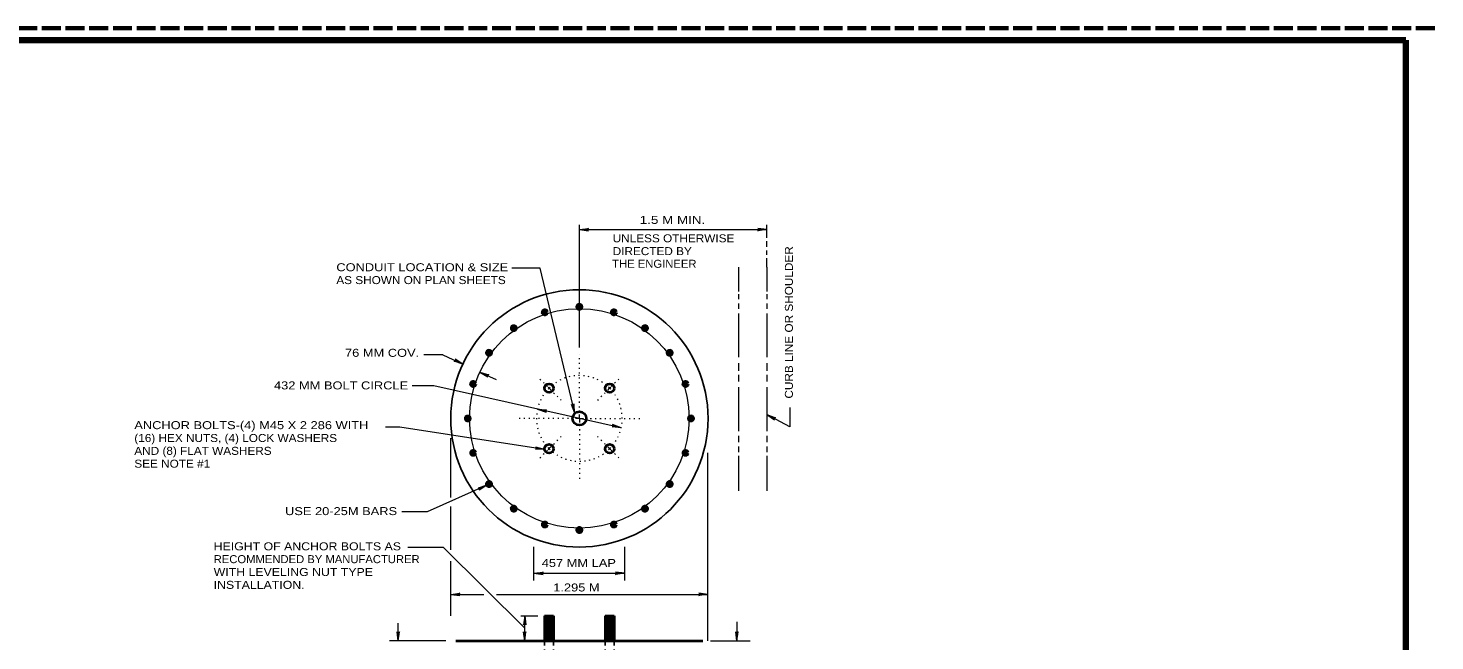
# Model space of a CAD drawing. Extents: x 312583 to 312853, y 144419 to 144586.
# Drawn here: x 312718.1 to 312851.8, y 144528 to 144586.2 of the extents above; entities that cross this region are included whole.
import ezdxf

# ---------------------------------------------------------------- set-up
doc = ezdxf.new("R2010")
doc.units = 0
doc.header["$LTSCALE"] = 0.3
for name, pattern in [('DOTTED', [1.5, 0.3, -1.2]), ('LONG_DASHED', [7.5, 6, -1.5]), ('SHORT_DASHED', [2.7, 1.5, -1.2])]:
    doc.linetypes.add(name, pattern=pattern)
doc.layers.add('1', color=7, linetype='Continuous', lineweight=13)
doc.layers.add('61', color=7, linetype='LONG_DASHED', lineweight=60)

msp = doc.modelspace()

# ---------------------------------------------------------------- linework, layer by layer
at = {"layer": '1', "lineweight": 158}
msp.add_line((312849, 144423.1446), (312849, 144585.0846), dxfattribs=at)
at = {"layer": '1'}
for p, q in [((312770.4975, 144555.8762), (312770.4975, 144567.5219)), ((312770.4975, 144567.0849), (312771.3638, 144567.1922)), ((312770.4975, 144567.0849), (312788.3148, 144567.0849)), ((312770.4975, 144567.0849), (312771.3638, 144566.9775)), ((312771.3638, 144567.1922), (312771.0878, 144567.0849)), ((312771.3638, 144566.9775), (312771.0878, 144567.0849)), ((312787.4485, 144567.1922), (312787.7245, 144567.0849)), ((312788.3148, 144567.0849), (312787.4485, 144567.1922)), ((312787.4485, 144566.9775), (312787.7245, 144567.0849)), ((312788.3148, 144567.0849), (312787.4485, 144566.9775)), ((312788.3148, 144566.3182), (312788.3148, 144567.5372)), ((312788.3148, 144565.4595), (312788.3148, 144565.9732)), ((312788.3148, 144564.6929), (312788.3148, 144565.1069)), ((312788.3148, 144563.5275), (312788.3148, 144564.3785)), ((312785.6085, 144563.5275), (312785.6085, 144561.2199)), ((312788.3148, 144563.5275), (312788.3148, 144561.2199)), ((312785.6085, 144560.9439), (312785.6085, 144560.4839)), ((312788.3148, 144560.9439), (312788.3148, 144560.4839)), ((312785.6085, 144560.0699), (312785.6085, 144559.5639)), ((312785.6085, 144559.1192), (312785.6085, 144554.9715)), ((312788.3148, 144560.0699), (312788.3148, 144559.5639)), ((312788.3148, 144559.1192), (312788.3148, 144554.9715)), ((312757.5408, 144555.1862), (312755.7162, 144555.1862)), ((312757.5408, 144555.1862), (312759.4192, 144554.3122)), ((312758.5912, 144554.5805), (312758.8825, 144554.5575)), ((312759.4192, 144554.3122), (312758.5912, 144554.5805)), ((312758.6832, 144554.7722), (312758.8825, 144554.5575)), ((312759.4192, 144554.3122), (312758.6832, 144554.7722)), ((312761.0522, 144553.5532), (312762.5778, 144552.8402)), ((312761.0522, 144553.5532), (312761.7882, 144553.0855)), ((312761.0522, 144553.5532), (312761.8802, 144553.2849)), ((312785.6085, 144554.4042), (312785.6085, 144553.6682)), ((312788.3148, 144554.4042), (312788.3148, 144553.6682)), ((312756.6668, 144552.2345), (312754.6045, 144552.2345)), ((312774.4688, 144548.2555), (312756.6668, 144552.2345)), ((312761.7882, 144553.0855), (312761.5812, 144553.3002)), ((312761.8802, 144553.2849), (312761.5812, 144553.3002)), ((312785.6085, 144553.3002), (312785.6085, 144552.6562)), ((312788.3148, 144553.3002), (312788.3148, 144552.6562)), ((312767.6148, 144552.0275), (312767.5152, 144552.1272)), ((312767.6148, 144552.0275), (312767.5152, 144551.9279)), ((312767.6148, 144552.0275), (312767.7145, 144552.1272)), ((312767.6148, 144552.0275), (312767.7145, 144551.9279)), ((312773.3725, 144552.0275), (312773.2728, 144552.1272)), ((312773.3725, 144552.0275), (312773.2728, 144551.9279)), ((312773.3725, 144552.0275), (312773.4798, 144552.1272)), ((312773.3725, 144552.0275), (312773.4798, 144551.9279)), ((312785.6085, 144552.1042), (312785.6085, 144547.9259)), ((312788.3148, 144552.1042), (312788.3148, 144547.9259)), ((312766.5185, 144550.0342), (312767.3388, 144549.7429)), ((312766.5185, 144550.0342), (312767.3848, 144549.9499)), ((312767.3848, 144549.9499), (312767.0935, 144549.9039)), ((312767.3388, 144549.7429), (312767.0935, 144549.9039)), ((312769.7615, 144550.4712), (312769.9302, 144550.2259)), ((312770.0682, 144549.6509), (312769.7615, 144550.4712)), ((312769.9762, 144550.5172), (312769.9302, 144550.2259)), ((312770.0682, 144549.6509), (312769.9762, 144550.5172)), ((312770.4975, 144549.1449), (312770.4975, 144549.5282)), ((312788.3148, 144549.5205), (312789.0278, 144549.0145)), ((312788.3148, 144549.5205), (312789.1275, 144549.1985)), ((312753.4315, 144548.3245), (312752.0668, 144548.3245)), ((312767.1932, 144546.1855), (312753.4315, 144548.3245)), ((312770.4975, 144549.1449), (312770.1142, 144549.1449)), ((312770.4975, 144549.1449), (312770.1142, 144549.1449)), ((312770.4975, 144549.1449), (312770.8808, 144549.1449)), ((312770.4975, 144549.1449), (312770.4975, 144548.7615)), ((312770.4975, 144549.1449), (312770.8808, 144549.1449)), ((312773.6025, 144548.3399), (312773.8938, 144548.3859)), ((312774.4688, 144548.2555), (312773.6025, 144548.3399)), ((312773.6485, 144548.5545), (312773.8938, 144548.3859)), ((312774.4688, 144548.2555), (312773.6485, 144548.5545)), ((312789.0278, 144549.0145), (312788.8362, 144549.2369)), ((312789.1275, 144549.1985), (312788.8362, 144549.2369)), ((312758.2768, 144541.6315), (312758.2768, 144547.2665)), ((312785.6085, 144547.4812), (312785.6085, 144546.9062)), ((312788.3148, 144547.4812), (312788.3148, 144546.9062)), ((312766.3192, 144546.2162), (312766.6105, 144546.2775)), ((312767.1932, 144546.1855), (312766.3192, 144546.2162)), ((312766.3498, 144546.4232), (312766.6105, 144546.2775)), ((312767.1932, 144546.1855), (312766.3498, 144546.4232)), ((312767.6148, 144546.2699), (312767.5152, 144546.3695)), ((312767.6148, 144546.2699), (312767.5152, 144546.1625)), ((312767.6148, 144546.2699), (312767.7145, 144546.3695)), ((312767.6148, 144546.2699), (312767.7145, 144546.1625)), ((312773.3725, 144546.2622), (312773.2728, 144546.3695)), ((312773.3725, 144546.2622), (312773.2728, 144546.1625)), ((312773.3725, 144546.2622), (312773.4798, 144546.3695)), ((312773.3725, 144546.2622), (312773.4798, 144546.1625)), ((312782.7105, 144528.0155), (312782.7105, 144545.8712)), ((312785.6085, 144546.4922), (312785.6085, 144545.9479)), ((312785.6085, 144545.6029), (312785.6085, 144542.2602)), ((312788.3148, 144546.4922), (312788.3148, 144545.9479)), ((312788.3148, 144545.6029), (312788.3148, 144542.2602)), ((312761.7038, 144542.8045), (312760.8758, 144542.5362)), ((312761.7038, 144542.8045), (312760.9678, 144542.3369)), ((312760.8758, 144542.5362), (312761.1672, 144542.5515)), ((312760.9678, 144542.3369), (312761.1672, 144542.5515)), ((312758.2768, 144536.6712), (312758.2768, 144540.7652)), ((312766.1812, 144533.7349), (312766.1812, 144536.9472)), ((312774.8062, 144533.7349), (312774.8062, 144536.9472)), ((312758.2768, 144530.9365), (312758.2768, 144535.5902)), ((312766.1812, 144534.4325), (312767.0475, 144534.5399)), ((312766.1812, 144534.4325), (312774.8062, 144534.4325)), ((312766.1812, 144534.4325), (312767.0475, 144534.3252)), ((312767.0475, 144534.5399), (312766.7715, 144534.4325)), ((312767.0475, 144534.3252), (312766.7715, 144534.4325)), ((312773.9398, 144534.5399), (312774.2158, 144534.4325)), ((312774.8062, 144534.4325), (312773.9398, 144534.5399)), ((312773.9398, 144534.3252), (312774.2158, 144534.4325)), ((312774.8062, 144534.4325), (312773.9398, 144534.3252)), ((312758.2768, 144530.3999), (312758.2768, 144532.7459)), ((312758.2768, 144532.4315), (312759.1432, 144532.5389)), ((312758.2768, 144532.4315), (312759.1432, 144532.3242)), ((312758.2768, 144532.4315), (312761.4202, 144532.4315)), ((312759.1432, 144532.5389), (312758.8672, 144532.4315)), ((312759.1432, 144532.3242), (312758.8672, 144532.4315)), ((312762.6085, 144532.4315), (312782.7105, 144532.4315)), ((312781.8442, 144532.5389), (312782.1202, 144532.4315)), ((312782.7105, 144532.4315), (312781.8442, 144532.5389)), ((312781.8442, 144532.3242), (312782.1202, 144532.4315)), ((312782.7105, 144532.4315), (312781.8442, 144532.3242)), ((312753.2935, 144528.0155), (312753.2935, 144529.6913)), ((312764.9468, 144530.4075), (312766.5492, 144530.4075)), ((312765.2995, 144530.4075), (312765.1922, 144529.5412)), ((312765.1922, 144529.5412), (312765.2995, 144529.8172)), ((312765.2995, 144528.0155), (312765.2995, 144530.4075)), ((312765.2995, 144530.4075), (312765.4068, 144529.5412)), ((312765.4068, 144529.5412), (312765.2995, 144529.8172)), ((312785.4552, 144529.8332), (312785.4552, 144528.0155)), ((312753.1862, 144528.8819), (312753.2935, 144528.6059)), ((312753.2935, 144528.0155), (312753.1862, 144528.8819)), ((312753.4008, 144528.8819), (312753.2935, 144528.6059)), ((312753.2935, 144528.0155), (312753.4008, 144528.8819)), ((312765.1922, 144528.8819), (312765.2995, 144528.6059)), ((312765.2995, 144528.0155), (312765.1922, 144528.8819)), ((312765.4068, 144528.8819), (312765.2995, 144528.6059)), ((312765.2995, 144528.0155), (312765.4068, 144528.8819)), ((312785.3478, 144528.8819), (312785.4552, 144528.6059)), ((312785.4552, 144528.0155), (312785.3478, 144528.8819)), ((312785.5625, 144528.8819), (312785.4552, 144528.6059)), ((312785.4552, 144528.0155), (312785.5625, 144528.8819)), ((312757.8092, 144528.0155), (312752.4502, 144528.0155)), ((312782.9635, 144528.0155), (312786.7202, 144528.0155))]:
    msp.add_line(p, q, dxfattribs=at)
at = {"layer": '1', "linetype": 'DOTTED'}
for p, q in [((312770.4975, 144549.7199), (312770.4975, 144555.2475)), ((312766.7485, 144552.8862), (312768.7878, 144550.8545)), ((312774.2388, 144552.8862), (312772.2072, 144550.8545)), ((312769.9225, 144549.1449), (312764.6478, 144549.1449)), ((312770.4975, 144548.5699), (312770.4975, 144543.3029)), ((312771.0725, 144549.1449), (312776.3395, 144549.1449)), ((312766.7485, 144545.4035), (312768.7878, 144547.4352)), ((312774.2388, 144545.4035), (312772.2072, 144547.4352))]:
    msp.add_line(p, q, dxfattribs=at)
at = {"layer": '1', "lineweight": 40}
for p, q in [((312767.1932, 144530.4075), (312768.0365, 144530.4075)), ((312767.1932, 144530.4075), (312767.1932, 144528.0155)), ((312767.1932, 144529.9322), (312768.0365, 144529.9322)), ((312767.1932, 144529.4492), (312768.0365, 144529.4492)), ((312767.3158, 144530.1699), (312767.9138, 144530.1699)), ((312767.3158, 144529.6869), (312767.9138, 144529.6869)), ((312768.0365, 144530.4075), (312768.0365, 144528.0155)), ((312772.9585, 144530.4075), (312773.7942, 144530.4075)), ((312772.9585, 144530.4075), (312772.9585, 144528.0155)), ((312772.9585, 144529.9322), (312773.7942, 144529.9322)), ((312772.9585, 144529.4492), (312773.7942, 144529.4492)), ((312773.0735, 144530.1699), (312773.6715, 144530.1699)), ((312773.0735, 144529.6869), (312773.6715, 144529.6869)), ((312773.7942, 144530.4075), (312773.7942, 144528.0155)), ((312767.1932, 144528.9739), (312768.0365, 144528.9739)), ((312767.1932, 144528.4909), (312768.0365, 144528.4909)), ((312767.3158, 144529.2115), (312767.9138, 144529.2115)), ((312767.3158, 144528.7285), (312767.9138, 144528.7285)), ((312767.3158, 144528.2532), (312767.9138, 144528.2532)), ((312772.9585, 144528.9739), (312773.7942, 144528.9739)), ((312772.9585, 144528.4909), (312773.7942, 144528.4909)), ((312773.0735, 144529.2115), (312773.6715, 144529.2115)), ((312773.0735, 144528.7285), (312773.6715, 144528.7285)), ((312773.0735, 144528.2532), (312773.6715, 144528.2532)), ((312758.7522, 144528.0155), (312782.2352, 144528.0155))]:
    msp.add_line(p, q, dxfattribs=at)
at = {"layer": '1', "linetype": 'SHORT_DASHED', "lineweight": 25}
for p, q in [((312767.1932, 144528.0155), (312767.1932, 144512.8815)), ((312768.0365, 144528.0155), (312768.0365, 144512.9429)), ((312772.9585, 144528.0155), (312772.9585, 144512.8815)), ((312773.7942, 144528.0155), (312773.7942, 144512.9429))]:
    msp.add_line(p, q, dxfattribs=at)
at = {"layer": '1', "lineweight": 158}
msp.add_lwpolyline([(312616.5, 144423.1446), (312616.5, 144585.0846), (312849, 144585.0846)], dxfattribs=at)
at = {"layer": '1'}
for points in [[(312770.0682, 144549.6509), (312766.7868, 144563.4355), (312764.0882, 144563.4355)], [(312790.4768, 144550.1952), (312790.4768, 144548.3399), (312788.3148, 144549.5205)], [(312761.7038, 144542.8045), (312756.0382, 144540.2745), (312753.6462, 144540.2745)], [(312765.2995, 144529.2115), (312757.5945, 144536.8782), (312754.1982, 144536.8782)]]:
    msp.add_lwpolyline(points, dxfattribs=at)
at = {"layer": '1', "lineweight": 25}
msp.add_circle((312770.4946, 144549.1458), 12.2188, dxfattribs=at)
at = {"layer": '1'}
msp.add_circle((312770.4946, 144549.1458), 10.4219, dxfattribs=at)
at = {"layer": '1', "lineweight": 60}
for centre, radius in [((312767.2181, 144559.228), 0.1797), ((312767.2181, 144559.228), 0.0898), ((312770.4946, 144559.7474), 0.1797), ((312770.4946, 144559.7474), 0.0898), ((312773.7712, 144559.2289), 0.1797), ((312773.7712, 144559.2289), 0.0898), ((312764.2631, 144557.722), 0.1797), ((312764.2631, 144557.722), 0.0898), ((312776.7267, 144557.7229), 0.1797), ((312776.7267, 144557.7229), 0.0898), ((312761.9175, 144555.3779), 0.1797), ((312761.9175, 144555.3779), 0.0898), ((312779.0708, 144555.3764), 0.1797), ((312779.0708, 144555.3764), 0.0898), ((312760.4115, 144552.4224), 0.1797), ((312760.4115, 144552.4224), 0.0898), ((312780.5768, 144552.4214), 0.1797), ((312780.5768, 144552.4214), 0.0898), ((312759.8931, 144549.1458), 0.1797), ((312759.8931, 144549.1458), 0.0898), ((312781.0962, 144549.1458), 0.1797), ((312781.0962, 144549.1458), 0.0898), ((312760.4115, 144545.8693), 0.1797), ((312760.4115, 144545.8693), 0.0898), ((312780.5777, 144545.8693), 0.1797), ((312780.5777, 144545.8693), 0.0898), ((312761.9175, 144542.9143), 0.1797), ((312761.9175, 144542.9143), 0.0898), ((312761.9175, 144542.9143), 0.0898), ((312779.0717, 144542.9138), 0.1797), ((312779.0717, 144542.9138), 0.0898), ((312764.2626, 144540.5687), 0.1797), ((312764.2626, 144540.5687), 0.0898), ((312776.7252, 144540.5687), 0.1797), ((312776.7252, 144540.5687), 0.0898), ((312767.2181, 144539.0627), 0.1797), ((312767.2181, 144539.0627), 0.0898), ((312773.7702, 144539.0627), 0.1797), ((312773.7702, 144539.0627), 0.0898), ((312770.4946, 144538.5443), 0.1797), ((312770.4946, 144538.5443), 0.0898)]:
    msp.add_circle(centre, radius, dxfattribs=at)
at = {"layer": '1', "lineweight": 40}
for centre, radius in [((312767.6144, 144552.0256), 0.4193), ((312773.3744, 144552.0256), 0.4193), ((312770.4946, 144549.1458), 0.6551), ((312767.6148, 144546.266), 0.4193), ((312773.3744, 144546.2656), 0.4193)]:
    msp.add_circle(centre, radius, dxfattribs=at)
at = {"layer": '1', "linetype": 'DOTTED'}
for start, end in [(50.9009, 129.10301), (140.89699, 219.0991), (320.9009, 39.10301), (231.57659, 309.0991)]:
    msp.add_arc((312770.4946, 144549.1458), 4.0729, start, end, dxfattribs=at)
at = {"layer": '61'}
msp.add_line((312851.75, 144586.2246), (312583.526, 144586.2246), dxfattribs=at)

# ---------------------------------------------------------------- texts
at = {"layer": '1'}
for s, width, p in [('1.5 M MIN.', 1.25, (312776.2341, 144567.6269)), ('UNLESS OTHERWISE ', 1.1, (312773.6597, 144565.8782)), ('THE ENGINEER', 1.05, (312773.6126, 144563.4585)), ('DIRECTED BY', 1.1, (312773.6597, 144564.6582)), ('CONDUIT LOCATION & SIZE ', 1.2, (312747.4109, 144563.1279)), ('AS SHOWN ON PLAN SHEETS', 1.1, (312747.4109, 144561.9079)), ('76 MM COV.', 1.2, (312748.234, 144554.9975)), ('432 MM BOLT CIRCLE', 1.2, (312741.4909, 144551.9032)), ('ANCHOR BOLTS-(4) M45 X 2 286 WITH', 1.2, (312728.2242, 144548.1265)), ('(16) HEX NUTS, (4) LOCK WASHERS', 1.1, (312728.2242, 144546.9065)), ('AND (8) FLAT WASHERS', 1.1, (312728.2242, 144545.6865)), ('SEE NOTE #1', 1.1, (312728.2242, 144544.4665)), ('USE 20-25M BARS', 1.2, (312742.5412, 144539.9608)), ('RECOMMENDED BY MANUFACTURER', 1.05, (312735.7606, 144535.3965)), ('HEIGHT OF ANCHOR BOLTS AS', 1.15, (312735.7606, 144536.6165)), ('WITH LEVELING NUT TYPE', 1.15, (312735.7606, 144534.1765)), ('457 MM LAP', 1.2, (312766.9184, 144535.0341)), ('INSTALLATION.', 1.15, (312735.7606, 144532.9565)), ('1.295 M', 1.2, (312768.0123, 144532.7072))]:
    msp.add_text(s, height=0.76, dxfattribs=dict(at, width=width)).set_placement(p)
at = {"layer": '1', "width": 1.1}
msp.add_text('CURB LINE OR SHOULDER', height=0.76, rotation=90, dxfattribs=at).set_placement((312790.7768, 144551.0309))

doc.saveas('drawing.dxf')
